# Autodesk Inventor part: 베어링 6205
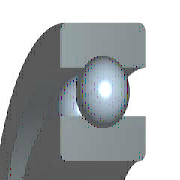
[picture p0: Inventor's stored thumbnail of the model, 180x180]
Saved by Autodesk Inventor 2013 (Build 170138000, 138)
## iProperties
IsCustomPart: 1
Company: 한국ATC센터
Created: 2014-10
Part Number: 베어링 6205
Material: 강철, 연강
Description: 깊은 그루브 볼 베어링
Document SubType Name: Modeling
Standard: KS B 2023
Designer: 한국ATC센터
Standards Organization: KS
Language: ko-KR
Size Designation: 6205 - 25 x 52 x 15
Categories: <MemberInstance><Categories><Category DisplayName="샤프트 부품" InternalName="7f7aeb1f-a693-4053-b835-cee3144e0d98" Mnemonic="SHFT"><Category DisplayName="베어링" Inter
Density: 7.86 g/cm^3
Mass: 129.543 g
Surface Area: 107.326 cm^2
Volume: 16.4813 cm^3
Author: KYOUNG IL JANG
Revision Number: 1
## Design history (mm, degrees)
sketch "스케치" dims "d0" = 7.02 (= -0.26 x WD + 0.26 x BD)
  geometry: L1 (3.99, 19.25)-(11.01, 19.25); L2 (7.5, 19.25)-(7.5, 15.74); L3 (7.5, 19.25)-(7.5, 22.76); L4 (4.892, 16.901)-(0, 16.901); L5 (0, 12.5)-(15, 12.5); L6 (4.892, 21.599)-(0, 21.599); L7 (0, 26)-(15, 26); L8 (15, 12.5)-(15, 16.901); L9 (10.108, 16.901)-(15, 16.901); L10 (10.108, 21.599)-(15, 21.599); L11 (15, 26)-(15, 21.599); L12 (-1.4, 0)-(8.4, 0) reference; L13 (0, -0.3)-(0, 5.3) reference
  constraints: 22 end point, 4 point on line, 2 collinear, 2 perpendicular, 2 symmetric about line, 1 midpoint, 1 parallel, 14 other
  dimensions: "d9" = 25 diameter of L5 L12 (= WD); "d11" = 52 diameter of L7 L12 (= BD); "d12" = 15 distance between parallel lines of L8 L13 (= KB); "d13" = 33.802 diameter of L9 L12 (= 0.326 x BD + 0.674 x WD)
revolve "본체" stored, may be unused: angle "d6" = 90 deg
revolve "볼" stored, may be unused: angle "d7" = 90 deg
pattern_circular "IDS_ARRAYBALL[SIMPL:T]" dims angle "d3" = 360 deg
body "Solid1"
fillet "모깎기1" dims "d1" = 1 (= KRS)
other parameters: "WD" = 25 [user parameter; used in 5 equation terms], "BD" = 52 [user parameter; used in 5 equation terms], "KB" = 15 [user parameter; used in 1 equation term], "KRS" = 1 [user parameter; used in 1 equation term], "d4" = 0, "d5" = 0, "d8" = 0, "d14" = 0, "d15" = 0, "BBA" = 0 [user parameter], "BC0" = 7800000 [user parameter], "BC" = 1.4e+07 [user parameter], "BR" = 26 (= 0.5 x BD) [user parameter], "WR" = 12.5 (= 0.5 x WD) [user parameter]
